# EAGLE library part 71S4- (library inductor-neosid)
FILTER adjustable filter transformer, type S
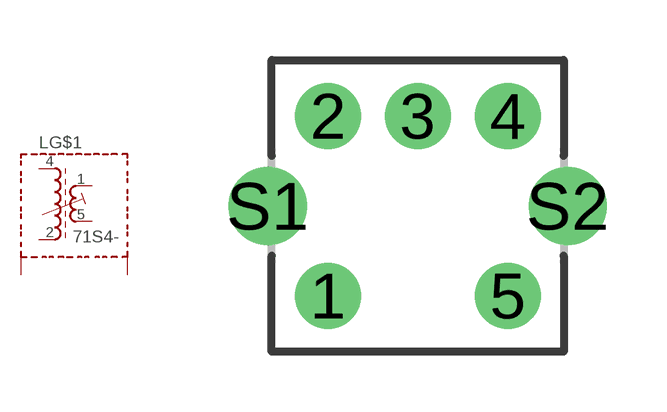
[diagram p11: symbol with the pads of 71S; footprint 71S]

Designator prefix L; gates G$1=SMF51-3 G$2=SHIELD3

## 71S4-4215 (OC_FARNELL: unknown; OC_NEWARK: unknown)  [71S]
1  G$1:A2  pas
2  G$1:E1  pas
4  G$1:A1  pas
5  G$1:E2  pas
S1  G$2:S1  pas
S2  G$2:S2  pas

## 71S4-1542 (OC_FARNELL: unknown; OC_NEWARK: unknown)  [71S]
1  G$1:A1  pas
2  G$1:A2  pas
4  G$1:E2  pas
5  G$1:E1  pas
S1  G$2:S1  pas
S2  G$2:S2  pas

## 71S4-2451 (OC_FARNELL: unknown; OC_NEWARK: unknown)  [71S]
1  G$1:E2  pas
2  G$1:A1  pas
4  G$1:E1  pas
5  G$1:A2  pas
S1  G$2:S1  pas
S2  G$2:S2  pas

## 71S4-4251 (OC_FARNELL: unknown; OC_NEWARK: unknown)  [71S]
1  G$1:E2  pas
2  G$1:E1  pas
4  G$1:A1  pas
5  G$1:A2  pas
S1  G$2:S1  pas
S2  G$2:S2  pas

## 71S4-2315 (OC_FARNELL: unknown; OC_NEWARK: unknown)  [71S]
1  G$1:A2  pas
2  G$1:A1  pas
3  G$1:E1  pas
5  G$1:E2  pas
S1  G$2:S1  pas
S2  G$2:S2  pas

## 71S4-5142 (OC_FARNELL: unknown; OC_NEWARK: unknown)  [71S]
1  G$1:E1  pas
2  G$1:E2  pas
4  G$1:A2  pas
5  G$1:A1  pas
S1  G$2:S1  pas
S2  G$2:S2  pas

## 71S4-5412 (OC_FARNELL: unknown; OC_NEWARK: unknown)  [71S]
1  G$1:A2  pas
2  G$1:E2  pas
4  G$1:E1  pas
5  G$1:A1  pas
S1  G$2:S1  pas
S2  G$2:S2  pas

## 71S4-1524 (OC_FARNELL: unknown; OC_NEWARK: unknown)  [71S]
Pads as for 71S

## 71S4-2143 (OC_FARNELL: unknown; OC_NEWARK: unknown)  [71S]
1  G$1:E1  pas
2  G$1:A1  pas
3  G$1:E2  pas
4  G$1:A2  pas
S1  G$2:S1  pas
S2  G$2:S2  pas

## 71S4-5123 (OC_FARNELL: unknown; OC_NEWARK: unknown)  [71S]
1  G$1:E1  pas
2  G$1:A2  pas
3  G$1:E2  pas
5  G$1:A1  pas
S1  G$2:S1  pas
S2  G$2:S2  pas

## 71S4-5241 (OC_FARNELL: unknown; OC_NEWARK: unknown)  [71S]
1  G$1:E2  pas
2  G$1:E1  pas
4  G$1:A2  pas
5  G$1:A1  pas
S1  G$2:S1  pas
S2  G$2:S2  pas

## 71S4-4512 (OC_FARNELL: unknown; OC_NEWARK: unknown)  [71S]
1  G$1:A2  pas
2  G$1:E2  pas
4  G$1:A1  pas
5  G$1:E1  pas
S1  G$2:S1  pas
S2  G$2:S2  pas

## 71S4-1532 (OC_FARNELL: unknown; OC_NEWARK: unknown)  [71S]
1  G$1:A1  pas
2  G$1:E2  pas
3  G$1:A2  pas
5  G$1:E1  pas
S1  G$2:S1  pas
S2  G$2:S2  pas

## 71S4-3254 (OC_FARNELL: unknown; OC_NEWARK: unknown)  [71S]
2  G$1:E1  pas
3  G$1:A1  pas
4  G$1:E2  pas
5  G$1:A2  pas
S1  G$2:S1  pas
S2  G$2:S2  pas

## 71S4-2415 (OC_FARNELL: unknown; OC_NEWARK: unknown)  [71S]
1  G$1:A2  pas
2  G$1:A1  pas
4  G$1:E1  pas
5  G$1:E2  pas
S1  G$2:S1  pas
S2  G$2:S2  pas

## Footprint 71S (pad centres in mm)
RF COIL ASSEMBLY 2 windings, 5 pads, grid 2.25 mm
drill 1.1 round: 1 -2.25,-2.25; 2 -2.25,2.25; 3 0,2.25; 4 2.25,2.25; 5 2.25,-2.25
drill 1.3 round: S1 -3.75,0; S2 3.75,0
